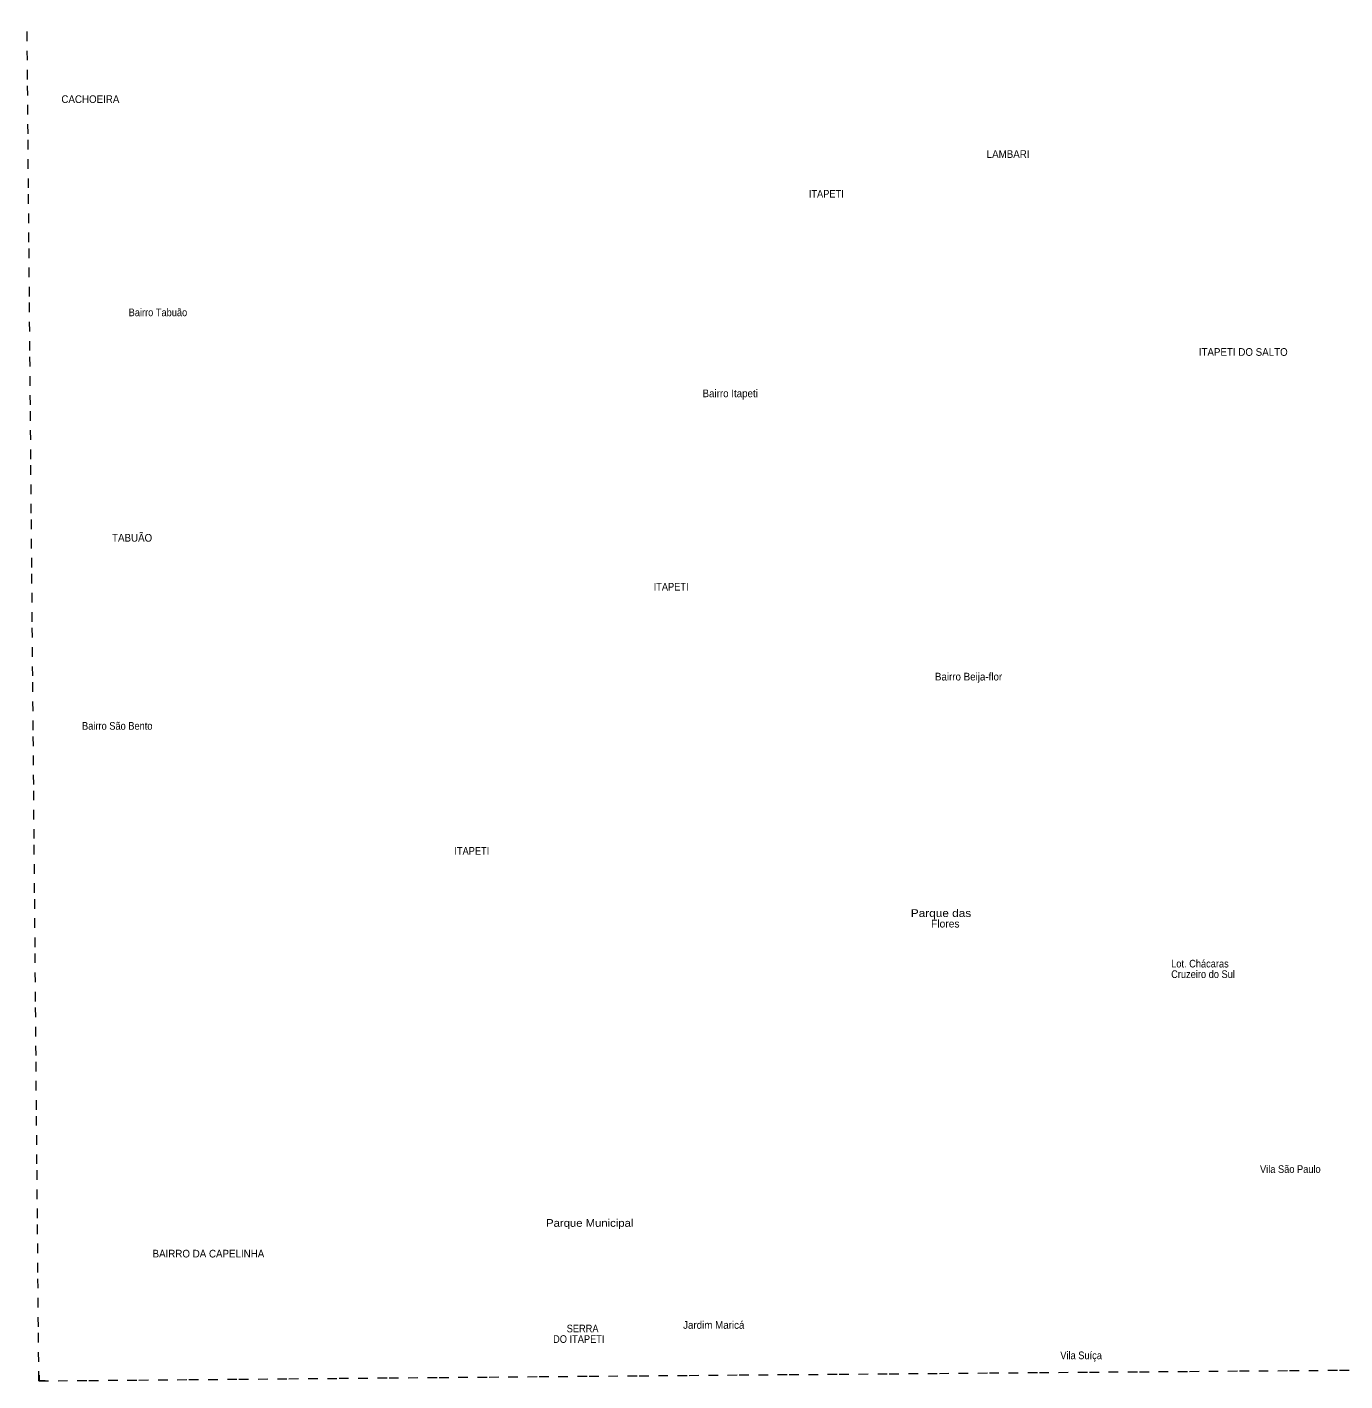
# Model space of a CAD drawing. Extents: x 372.1 to 397.9, y 7400.6 to 7428.4.
# Drawn here: x 372.24 to 385.97, y 7400.56 to 7414.67 of the extents above; entities that cross this region are included whole.
import ezdxf
from ezdxf.enums import TextEntityAlignment as Align

# ---------------------------------------------------------------- set-up
doc = ezdxf.new("R2010")
doc.units = 0
doc.header["$LTSCALE"] = 0.032
doc.linetypes.add('SHORT_DASHED', pattern=[2.7, 1.5, -1.2])
doc.layers.add('46', color=7, linetype='SHORT_DASHED', lineweight=13)
doc.layers.add('63', color=7, linetype='Continuous', lineweight=25)
doc.layers.add('61', color=7, linetype='Continuous')

msp = doc.modelspace()

# ---------------------------------------------------------------- linework, layer by layer
at = {"layer": '46'}
for points in [[(372.3673, 7400.5644), (372.3624, 7401.1293), (372.3575, 7401.6942), (372.3526, 7402.2591), (372.3477, 7402.8241), (372.3427, 7403.389), (372.3378, 7403.9539), (372.3329, 7404.5188), (372.328, 7405.0838), (372.3231, 7405.6487), (372.3182, 7406.2136), (372.3133, 7406.7785), (372.3084, 7407.3434), (372.3035, 7407.9084), (372.2986, 7408.4733), (372.2937, 7409.0382), (372.2888, 7409.6031), (372.2839, 7410.168), (372.279, 7410.733), (372.2741, 7411.2979), (372.2692, 7411.8628), (372.2643, 7412.4277), (372.2594, 7412.9926), (372.2545, 7413.5575), (372.2496, 7414.1225), (372.2447, 7414.6874)], [(372.3673, 7400.5644), (372.8883, 7400.5689), (373.4093, 7400.5734), (373.9303, 7400.5779), (374.4513, 7400.5824), (374.9723, 7400.5868), (375.4933, 7400.5912), (376.0143, 7400.5956), (376.5353, 7400.6), (377.0563, 7400.6044), (377.5773, 7400.6088), (378.0983, 7400.6131), (378.6193, 7400.6174), (379.1403, 7400.6217), (379.6613, 7400.626), (380.1823, 7400.6303), (380.7033, 7400.6345), (381.2243, 7400.6388), (381.7453, 7400.643), (382.2663, 7400.6472), (382.7873, 7400.6513), (383.3083, 7400.6555), (383.8293, 7400.6596), (384.3503, 7400.6637), (384.8713, 7400.6678), (385.3923, 7400.6719), (385.9132, 7400.676), (386.4342, 7400.68)]]:
    msp.add_lwpolyline(points, dxfattribs=at)
at = {"layer": '63'}
msp.add_lwpolyline([(372.3719, 7400.6257), (372.3719, 7400.5641), (372.4326, 7400.5641)], dxfattribs=at)

# ---------------------------------------------------------------- texts
at = {"layer": '61'}
for s, width, p in [('CACHOEIRA', 0.95, (372.9039, 7413.878)), ('LAMBARI', 0.95, (382.4616, 7413.3059)), ('ITAPETI', 0.9, (380.5682, 7412.8917)), ('ITAPETI DO SALTO', 0.95, (384.9101, 7411.244)), ('TABUÃO', 0.95, (373.3386, 7409.3081)), ('ITAPETI', 0.9, (378.952, 7408.798)), ('ITAPETI', 0.9, (376.8763, 7406.0462)), ('Parque das', 1.15, (381.7627, 7405.398)), ('Parque Municipal', 1.1, (378.1044, 7402.1697)), ('BAIRRO DA CAPELINHA', 0.95, (374.1332, 7401.8503)), ('   SERRA', 0.9, (377.9903, 7401.0702)), ('DO ITAPETI', 0.9, (377.9903, 7400.9602))]:
    msp.add_text(s, height=0.08, dxfattribs=dict(at, width=width)).set_placement(p, align=Align.CENTER)
at = {"layer": '61', "width": 0.9}
msp.add_text('Bairro Tabuão', height=0.08, dxfattribs=at).set_placement((373.9121, 7411.6567), align=Align.RIGHT)
at = {"layer": '61'}
for s, width, p in [('Bairro Itapeti', 0.95, (379.2791, 7410.8127)), ('Bairro Beija-flor', 0.95, (381.6994, 7407.8617)), ('Bairro São Bento', 0.9, (372.8172, 7407.3485)), ('Lot. Chácaras', 0.9, (384.1597, 7404.8717)), ('Cruzeiro do Sul', 0.9, (384.1597, 7404.7617)), ('Vila São Paulo', 0.9, (385.0851, 7402.7309)), ('Jardim Maricá', 0.95, (379.0772, 7401.1071)), ('Vila Suíça', 0.9, (383.005, 7400.7905))]:
    msp.add_text(s, height=0.08, dxfattribs=dict(at, width=width)).set_placement(p)
msp.add_text('   Flores', height=0.08, dxfattribs=at).set_placement((381.7628, 7405.288), align=Align.CENTER)

doc.saveas('drawing.dxf')
